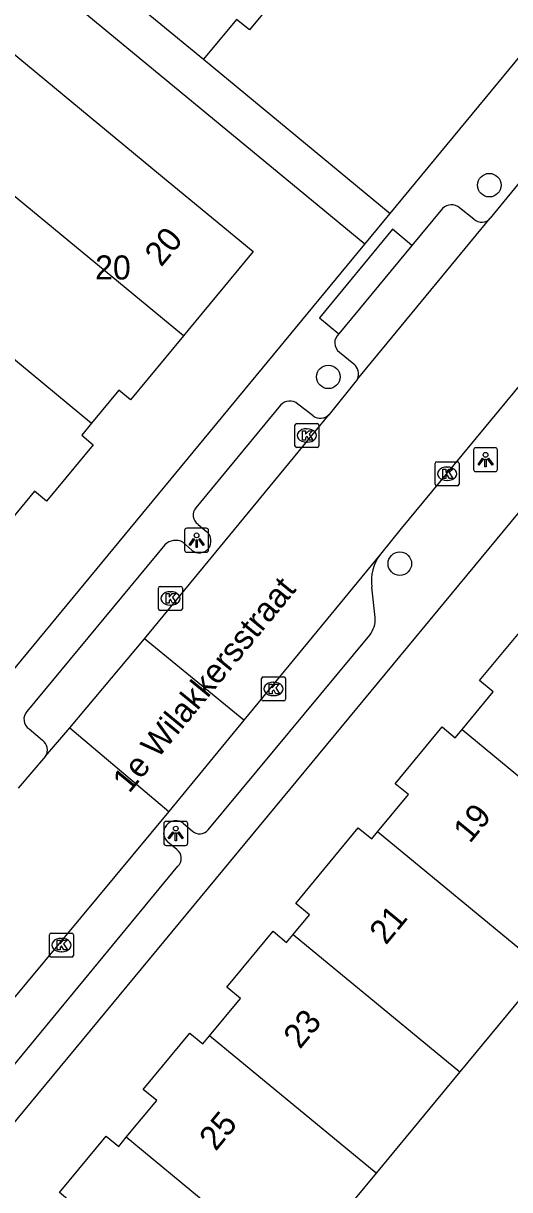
# Model space of a CAD drawing. Extents: x 162074 to 163034, y 381824 to 382557.
# Drawn here: x 162330.07 to 162350.3, y 382106.65 to 382155.17 of the extents above; entities that cross this region are included whole.
import ezdxf

# ---------------------------------------------------------------- set-up
doc = ezdxf.new("R2010")
doc.units = 0
for name, color, linetype in [('IMGEO_Boom', 7, 'Continuous'), ('IMGEO_Kolk', 7, 'Continuous'), ('IMGEO_Lichtpunt', 7, 'Continuous'), ('IMGEO_Openbare_ruimte_label', 7, 'Continuous'), ('IMGEO_Pand', 7, 'Continuous'), ('IMGEO_Pand_nummerreeks', 7, 'Continuous'), ('IMGEO_Rijbaan_lokaal_open', 7, 'Continuous'), ('IMGEO_Voetpad_open', 7, 'Continuous')]:
    doc.layers.add(name, color=color, linetype=linetype)

msp = doc.modelspace()

# ---------------------------------------------------------------- linework, layer by layer
at = {"layer": 'IMGEO_Boom'}
for centre in [(162349.458, 382148.436), (162342.759, 382140.461), (162345.734, 382132.69)]:
    msp.add_circle(centre, 0.489, dxfattribs=at)
at = {"layer": 'IMGEO_Kolk'}
for p, q in [((162341.368, 382137.596), (162341.368, 382138.448)), ((162341.443, 382138.522), (162342.295, 382138.522)), ((162341.856, 382138.302), (162341.881, 382138.302)), ((162342.369, 382138.448), (162342.369, 382137.596)), ((162341.879, 382137.742), (162341.854, 382137.742)), ((162342.295, 382137.522), (162341.443, 382137.522)), ((162347.201, 382136.002), (162347.201, 382136.854)), ((162347.276, 382136.928), (162348.128, 382136.928)), ((162348.202, 382136.854), (162348.202, 382136.002)), ((162347.689, 382136.708), (162347.714, 382136.708)), ((162348.128, 382135.928), (162347.276, 382135.928)), ((162347.712, 382136.148), (162347.687, 382136.148)), ((162335.689, 382130.816), (162335.689, 382131.668)), ((162335.764, 382131.742), (162336.616, 382131.742)), ((162336.177, 382131.522), (162336.202, 382131.522)), ((162336.69, 382131.668), (162336.69, 382130.816)), ((162336.2, 382130.962), (162336.175, 382130.962)), ((162336.616, 382130.742), (162335.764, 382130.742)), ((162339.98, 382127.054), (162339.98, 382127.906)), ((162340.055, 382127.98), (162340.907, 382127.98)), ((162340.468, 382127.76), (162340.493, 382127.76)), ((162340.981, 382127.906), (162340.981, 382127.054)), ((162340.491, 382127.2), (162340.466, 382127.2)), ((162340.907, 382126.98), (162340.055, 382126.98)), ((162331.157, 382116.395), (162331.157, 382117.247)), ((162331.232, 382117.321), (162332.084, 382117.321)), ((162331.645, 382117.101), (162331.67, 382117.101)), ((162332.158, 382117.247), (162332.158, 382116.395)), ((162331.668, 382116.541), (162331.643, 382116.541)), ((162332.084, 382116.321), (162331.232, 382116.321))]:
    msp.add_line(p, q, dxfattribs=at)
for points in [[(162341.368, 382137.596), (162341.368, 382138.448)], [(162341.443, 382138.522), (162342.295, 382138.522)], [(162341.689, 382138.222), (162341.812, 382138.222), (162341.812, 382138.071), (162341.942, 382138.222), (162342.106, 382138.222), (162341.96, 382138.071), (162342.113, 382137.822), (162341.961, 382137.822), (162341.876, 382137.986), (162341.812, 382137.919), (162341.812, 382137.822), (162341.689, 382137.822), (162341.689, 382138.222)], [(162342.369, 382138.448), (162342.369, 382137.596)], [(162342.295, 382137.522), (162341.443, 382137.522)], [(162347.201, 382136.002), (162347.201, 382136.854)], [(162347.276, 382136.928), (162348.128, 382136.928)], [(162348.202, 382136.854), (162348.202, 382136.002)], [(162347.522, 382136.628), (162347.645, 382136.628), (162347.645, 382136.477), (162347.775, 382136.628), (162347.939, 382136.628), (162347.793, 382136.477), (162347.946, 382136.228), (162347.794, 382136.228), (162347.709, 382136.392), (162347.645, 382136.325), (162347.645, 382136.228), (162347.522, 382136.228), (162347.522, 382136.628)], [(162348.128, 382135.928), (162347.276, 382135.928)], [(162335.689, 382130.816), (162335.689, 382131.668)], [(162335.764, 382131.742), (162336.616, 382131.742)], [(162336.01, 382131.442), (162336.133, 382131.442), (162336.133, 382131.291), (162336.263, 382131.442), (162336.427, 382131.442), (162336.281, 382131.291), (162336.434, 382131.042), (162336.282, 382131.042), (162336.197, 382131.206), (162336.133, 382131.139), (162336.133, 382131.042), (162336.01, 382131.042), (162336.01, 382131.442)], [(162336.69, 382131.668), (162336.69, 382130.816)], [(162336.616, 382130.742), (162335.764, 382130.742)], [(162339.98, 382127.054), (162339.98, 382127.906)], [(162340.055, 382127.98), (162340.907, 382127.98)], [(162340.301, 382127.68), (162340.424, 382127.68), (162340.424, 382127.529), (162340.554, 382127.68), (162340.718, 382127.68), (162340.572, 382127.529), (162340.725, 382127.28), (162340.573, 382127.28), (162340.488, 382127.444), (162340.424, 382127.377), (162340.424, 382127.28), (162340.301, 382127.28), (162340.301, 382127.68)], [(162340.981, 382127.906), (162340.981, 382127.054)], [(162340.907, 382126.98), (162340.055, 382126.98)], [(162331.157, 382116.395), (162331.157, 382117.247)], [(162331.232, 382117.321), (162332.084, 382117.321)], [(162331.478, 382117.021), (162331.601, 382117.021), (162331.601, 382116.87), (162331.731, 382117.021), (162331.895, 382117.021), (162331.749, 382116.87), (162331.902, 382116.621), (162331.75, 382116.621), (162331.665, 382116.785), (162331.601, 382116.718), (162331.601, 382116.621), (162331.478, 382116.621), (162331.478, 382117.021)], [(162332.158, 382117.247), (162332.158, 382116.395)], [(162332.084, 382116.321), (162331.232, 382116.321)]]:
    msp.add_lwpolyline(points, dxfattribs=at)
for centre, start, end in [((162341.445, 382138.446), 91.552, 178.448), ((162341.445, 382138.446), 91.552, 178.448), ((162342.293, 382138.446), 1.552, 88.448), ((162342.293, 382138.446), 1.552, 88.448), ((162341.445, 382137.598), 181.552, 268.448), ((162341.445, 382137.598), 181.552, 268.448), ((162342.293, 382137.598), 271.552, 358.448), ((162342.293, 382137.598), 271.552, 358.448), ((162347.278, 382136.852), 91.552, 178.448), ((162347.278, 382136.852), 91.552, 178.448), ((162348.126, 382136.852), 1.552, 88.448), ((162348.126, 382136.852), 1.552, 88.448), ((162347.278, 382136.004), 181.552, 268.448), ((162347.278, 382136.004), 181.552, 268.448), ((162348.126, 382136.004), 271.552, 358.448), ((162348.126, 382136.004), 271.552, 358.448), ((162335.766, 382131.666), 91.552, 178.448), ((162335.766, 382131.666), 91.552, 178.448), ((162336.614, 382131.666), 1.552, 88.448), ((162336.614, 382131.666), 1.552, 88.448), ((162335.766, 382130.818), 181.552, 268.448), ((162335.766, 382130.818), 181.552, 268.448), ((162336.614, 382130.818), 271.552, 358.448), ((162336.614, 382130.818), 271.552, 358.448), ((162340.057, 382127.904), 91.552, 178.448), ((162340.057, 382127.904), 91.552, 178.448), ((162340.905, 382127.904), 1.552, 88.448), ((162340.905, 382127.904), 1.552, 88.448), ((162340.057, 382127.056), 181.552, 268.448), ((162340.057, 382127.056), 181.552, 268.448), ((162340.905, 382127.056), 271.552, 358.448), ((162340.905, 382127.056), 271.552, 358.448), ((162331.234, 382117.245), 91.552, 178.448), ((162331.234, 382117.245), 91.552, 178.448), ((162332.082, 382117.245), 1.552, 88.448), ((162332.082, 382117.245), 1.552, 88.448), ((162331.234, 382116.397), 181.552, 268.448), ((162331.234, 382116.397), 181.552, 268.448), ((162332.082, 382116.397), 271.552, 358.448), ((162332.082, 382116.397), 271.552, 358.448)]:
    msp.add_arc(centre, 0.0765, start, end, dxfattribs=at)
for centre, major_axis, ratio, start_param, end_param in [((162341.855, 382138.022), (-0.387, 0.002), 0.722429, 4.712389, 7.853982), ((162341.88, 382138.022), (-0.39, 0.002), 0.717154, 1.570796, 4.712389), ((162347.688, 382136.428), (-0.387, 0.002), 0.722429, 4.712389, 7.853982), ((162347.713, 382136.428), (-0.39, 0.002), 0.717154, 1.570796, 4.712389), ((162336.176, 382131.242), (-0.387, 0.002), 0.722429, 4.712389, 7.853982), ((162336.201, 382131.242), (-0.39, 0.002), 0.717154, 1.570796, 4.712389), ((162340.467, 382127.48), (-0.387, 0.002), 0.722429, 4.712389, 7.853982), ((162340.492, 382127.48), (-0.39, 0.002), 0.717154, 1.570796, 4.712389), ((162331.644, 382116.821), (-0.387, 0.002), 0.722429, 4.712389, 7.853982), ((162331.669, 382116.821), (-0.39, 0.002), 0.717154, 1.570796, 4.712389)]:
    msp.add_ellipse(centre, major_axis=major_axis, ratio=ratio, start_param=start_param, end_param=end_param, dxfattribs=at)
at = {"layer": 'IMGEO_Lichtpunt'}
for p, q in [((162348.801, 382137.419), (162348.801, 382136.612)), ((162348.801, 382137.419), (162348.801, 382136.612)), ((162349.703, 382137.514), (162348.895, 382137.514)), ((162349.703, 382137.514), (162348.895, 382137.514)), ((162349.797, 382136.612), (162349.797, 382137.419)), ((162349.797, 382136.612), (162349.797, 382137.419)), ((162348.895, 382136.518), (162349.703, 382136.518)), ((162348.895, 382136.518), (162349.703, 382136.518)), ((162336.78, 382134.069), (162336.78, 382133.262)), ((162336.78, 382134.069), (162336.78, 382133.262)), ((162337.682, 382134.164), (162336.874, 382134.164)), ((162337.682, 382134.164), (162336.874, 382134.164)), ((162337.776, 382133.262), (162337.776, 382134.069)), ((162337.776, 382133.262), (162337.776, 382134.069)), ((162336.874, 382133.168), (162337.682, 382133.168)), ((162336.874, 382133.168), (162337.682, 382133.168)), ((162335.914, 382121.871), (162335.914, 382121.064)), ((162335.914, 382121.871), (162335.914, 382121.064)), ((162336.816, 382121.966), (162336.008, 382121.966)), ((162336.816, 382121.966), (162336.008, 382121.966)), ((162336.91, 382121.064), (162336.91, 382121.871)), ((162336.91, 382121.064), (162336.91, 382121.871)), ((162336.008, 382120.97), (162336.816, 382120.97)), ((162336.008, 382120.97), (162336.816, 382120.97))]:
    msp.add_line(p, q, dxfattribs=at)
for points in [[(162349.175, 382137.083), (162349.214, 382137.055), (162349.026, 382136.793), (162348.988, 382136.82), (162349.175, 382137.083)], [(162349.277, 382137.035), (162349.324, 382137.035), (162349.324, 382136.713), (162349.277, 382136.713), (162349.277, 382137.035)], [(162349.387, 382137.055), (162349.425, 382137.082), (162349.612, 382136.82), (162349.573, 382136.792), (162349.387, 382137.055)], [(162337.154, 382133.733), (162337.193, 382133.705), (162337.005, 382133.443), (162336.967, 382133.47), (162337.154, 382133.733)], [(162337.256, 382133.685), (162337.303, 382133.685), (162337.303, 382133.363), (162337.256, 382133.363), (162337.256, 382133.685)], [(162337.366, 382133.705), (162337.404, 382133.732), (162337.591, 382133.47), (162337.552, 382133.442), (162337.366, 382133.705)], [(162336.288, 382121.535), (162336.327, 382121.507), (162336.139, 382121.245), (162336.101, 382121.272), (162336.288, 382121.535)], [(162336.39, 382121.487), (162336.437, 382121.487), (162336.437, 382121.165), (162336.39, 382121.165), (162336.39, 382121.487)], [(162336.5, 382121.507), (162336.538, 382121.534), (162336.725, 382121.272), (162336.686, 382121.244), (162336.5, 382121.507)]]:
    msp.add_lwpolyline(points, dxfattribs=at)
for centre in [(162349.3, 382137.217), (162337.279, 382133.867), (162336.413, 382121.669)]:
    msp.add_circle(centre, 0.0994, dxfattribs=at)
for centre, start, end in [((162348.895, 382137.419), 90, 180), ((162348.895, 382137.419), 90, 180), ((162349.703, 382137.419), 0, 90), ((162349.703, 382137.419), 0, 90), ((162348.895, 382136.612), 180, 270), ((162348.895, 382136.612), 180, 270), ((162349.703, 382136.612), 270, 0), ((162349.703, 382136.612), 270, 360), ((162336.874, 382134.069), 90, 180), ((162336.874, 382134.069), 90, 180), ((162337.682, 382134.069), 0, 90), ((162337.682, 382134.069), 0, 90), ((162336.874, 382133.262), 180, 270), ((162336.874, 382133.262), 180, 270), ((162337.682, 382133.262), 270, 0), ((162337.682, 382133.262), 270, 360), ((162336.008, 382121.871), 90, 180), ((162336.008, 382121.871), 90, 180), ((162336.816, 382121.871), 0, 90), ((162336.816, 382121.871), 0, 90), ((162336.008, 382121.064), 180, 270), ((162336.008, 382121.064), 180, 270), ((162336.816, 382121.064), 270, 0), ((162336.816, 382121.064), 270, 360)]:
    msp.add_arc(centre, 0.0946, start, end, dxfattribs=at)
at = {"layer": 'IMGEO_Pand'}
for points in [[(162330.664, 382159.38), (162333.717, 382156.859), (162337.573, 382153.676)], [(162341.191, 382158.054), (162340.84, 382157.628), (162341.372, 382157.189), (162339.477, 382154.894), (162338.943, 382155.335), (162337.573, 382153.676)], [(162329.26, 382148.338), (162324.766, 382152.048), (162324.954, 382152.276), (162327.662, 382155.556), (162335.775, 382148.858), (162339.631, 382145.675), (162336.921, 382142.391), (162336.734, 382142.165)], [(162336.734, 382142.165), (162329.26, 382148.338)], [(162325.929, 382144.303), (162332.914, 382138.534)], [(162336.734, 382142.165), (162334.533, 382139.499), (162334.044, 382139.903), (162332.914, 382138.534)], [(162332.914, 382138.534), (162332.499, 382138.032), (162332.977, 382137.637), (162331.039, 382135.289), (162330.531, 382135.709), (162329.366, 382134.298)], [(162348.325, 382125.789), (162349.62, 382127.357), (162349.055, 382127.824), (162351.194, 382130.411)], [(162344.811, 382121.537), (162346.088, 382123.081), (162345.541, 382123.533), (162347.495, 382125.897), (162348.041, 382125.446), (162348.325, 382125.789)], [(162348.325, 382125.789), (162355.268, 382120.061)], [(162341.302, 382117.265), (162341.981, 382118.086), (162341.411, 382118.558), (162344.007, 382121.699), (162344.564, 382121.238), (162344.811, 382121.537)], [(162351.751, 382115.808), (162344.811, 382121.537)], [(162337.819, 382113.05), (162339.101, 382114.6), (162338.538, 382115.065), (162340.464, 382117.395), (162341.026, 382116.93), (162341.302, 382117.265)], [(162341.302, 382117.265), (162348.229, 382111.548)], [(162351.751, 382115.808), (162348.229, 382111.548)], [(162334.355, 382108.824), (162335.62, 382110.353), (162335.061, 382110.815), (162336.999, 382113.16), (162337.54, 382112.713), (162337.819, 382113.05)], [(162344.747, 382107.336), (162337.819, 382113.05)], [(162348.229, 382111.548), (162344.747, 382107.336)], [(162330.857, 382104.607), (162332.094, 382106.102), (162331.578, 382106.528), (162333.518, 382108.874), (162334.04, 382108.443), (162334.355, 382108.824)], [(162341.26, 382103.119), (162334.355, 382108.824)], [(162344.747, 382107.336), (162341.26, 382103.119)]]:
    msp.add_lwpolyline(points, dxfattribs=at)
at = {"layer": 'IMGEO_Rijbaan_lokaal_open'}
for points in [[(162351.516, 382149.53), (162349.496, 382147.059)], [(162343.976, 382140.371), (162349.496, 382147.059)], [(162343.976, 382140.371), (162342.788, 382138.891)], [(162351.1, 382140.57), (162345.792, 382134.155), (162344.927, 382133.085)], [(162335.106, 382129.564), (162342.788, 382138.891)], [(162344.927, 382133.085), (162339.238, 382126.178)], [(162332.008, 382125.861), (162335.106, 382129.564)], [(162339.238, 382126.178), (162335.106, 382129.564)], [(162339.238, 382126.178), (162336.118, 382122.382)], [(162331, 382124.675), (162332.008, 382125.861)], [(162332.008, 382125.861), (162336.118, 382122.382)], [(162331, 382124.675), (162329.86, 382123.349)], [(162336.118, 382122.382), (162316.921, 382099.281)]]:
    msp.add_lwpolyline(points, dxfattribs=at)
at = {"layer": 'IMGEO_Voetpad_open'}
for points in [[(162345.338, 382147.264), (162373.579, 382181.474)], [(162344.282, 382145.986), (162324.785, 382162.075), (162318.898, 382154.941)], [(162337.573, 382153.676), (162345.338, 382147.264)], [(162347.516, 382147.47), (162346.24, 382145.931)], [(162348.819, 382147.02), (162348.222, 382147.495)], [(162344.282, 382145.986), (162345.338, 382147.264)], [(162346.24, 382145.931), (162345.429, 382146.605), (162342.39, 382142.922), (162343.195, 382142.252)], [(162292.703, 382083.506), (162344.282, 382145.986)], [(162346.24, 382145.931), (162343.195, 382142.252)], [(162343.221, 382141.484), (162343.822, 382141.003)], [(162340.772, 382139.286), (162337.248, 382135.014)], [(162342.129, 382138.843), (162341.487, 382139.331)], [(162352.042, 382136.478), (162351.891, 382136.294), (162317.774, 382095.055)], [(162337.34, 382134.326), (162337.702, 382134.015)], [(162335.964, 382133.472), (162330.223, 382126.543)], [(162337.08, 382133.245), (162336.712, 382133.585)], [(162344.708, 382130.453), (162344.569, 382131.715)], [(162337.764, 382121.621), (162344.483, 382129.717)], [(162330.318, 382125.812), (162330.867, 382125.347)], [(162336.731, 382121.879), (162337.09, 382121.58)], [(162336.46, 382120.798), (162336.084, 382121.108)], [(162320.226, 382100.372), (162336.497, 382120.103)]]:
    msp.add_lwpolyline(points, dxfattribs=at)
for centre, radius, start, end in [((162347.883, 382147.09), 0.528, 50.0271, 134.0289), ((162349.139, 382147.357), 0.465, 226.4909, 320.1031), ((162343.528, 382141.879), 0.5, 131.7101, 232.1679), ((162343.481, 382140.585), 0.539, 336.5943, 50.7946), ((162341.152, 382138.949), 0.508, 48.7567, 138.4459), ((162342.433, 382139.216), 0.481, 230.8041, 317.5278), ((162337.592, 382134.71), 0.459, 138.5528, 236.6801), ((162337.384, 382133.636), 0.495, 232.1459, 49.9921), ((162336.413, 382133.029), 0.631, 61.7589, 135.4224), ((162346.379, 382131.974), 1.829, 142.577, 188.1336), ((162343.642, 382130.377), 1.069, 321.9074, 4.0951), ((162330.58, 382126.218), 0.483, 137.6301, 237.1791), ((162330.581, 382124.941), 0.496, 327.5416, 54.8487), ((162336.41, 382121.491), 0.503, 50.4071, 229.5882), ((162337.409, 382121.897), 0.449, 224.7902, 322.172), ((162336.196, 382120.435), 0.448, 312.1187, 53.9761)]:
    msp.add_arc(centre, radius, start, end, dxfattribs=at)

# ---------------------------------------------------------------- texts
at = {"layer": 'IMGEO_Openbare_ruimte_label'}
msp.add_text('1e Wilakkersstraat', height=1, rotation=50.5978, dxfattribs=at).set_placement((162334.476, 382123.107))
at = {"layer": 'IMGEO_Pand_nummerreeks'}
for s, rotation, p in [('20', 50.4701, (162335.808, 382145.002)), ('20', 0, (162333.054, 382144.513)), ('19', 50.4603, (162348.646, 382121.022)), ('21', 50.4603, (162345.156, 382116.794)), ('23', 50.4603, (162341.579, 382112.462)), ('25', 50.4603, (162338.075, 382108.216))]:
    msp.add_text(s, height=1, rotation=rotation, dxfattribs=at).set_placement(p)

doc.saveas('drawing.dxf')
